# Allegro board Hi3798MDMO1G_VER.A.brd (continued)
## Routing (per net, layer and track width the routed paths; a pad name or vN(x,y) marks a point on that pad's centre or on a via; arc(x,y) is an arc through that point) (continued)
DDR_DQ11: length 9.7
  TOP w0.127: U1.169 43.2,43.38 42,44.58 42,45.72 41.5,46.23 39.46,46.23 39.08,45.84 39.08,44.65 U3.C2
DDR_DQ12: length 7.8
  TOP w0.127: U1.188 42.68,35.78 41.88,36.58 41.88,39.88 41.5,40.25 U3.A7
DDR_DQ13: length 5.3
  TOP w0.127: v2(43.66,42.55) 43.92,42.55 44.29,42.18 U1.172 ; U3.A2 v2(41.47,44.65)
  BOTTOM w0.127: v2(43.66,42.55) 43.66,42.8 41.8,44.65 v2(41.47,44.65)
DDR_DQ14: length 8.7
  TOP w0.127: U3.B8 40.67,39.85 41.27,39.85 41.5,39.62 41.5,36.32 42.44,35.38 U1.189
DDR_DQ15: length 5.1
  TOP w0.127: v2(42.64,42.55) 43.27,41.91 44.03,41.91 44.16,41.78 U1.173 ; U3.A3 v2(41.47,43.85)
  BOTTOM w0.127: v2(41.47,43.85) 41.47,43.72 v2(42.64,42.55)
DDR_DQ16: length 10.3
  TOP w0.127: U6.E3 v2(37.47,27.44) ; U1.201 44.06,30.58 43.81,30.83 v2(42.08,30.83)
  BOTTOM w0.127: v2(37.47,27.44) 37.47,28.1 38.19,28.83 38.19,29.34 39.69,30.83 v2(42.08,30.83)
DDR_DQ17: length 17.5
  TOP w0.127: U6.F7 37.46,23.45 37.46,22.83 37.63,22.66 38.11,22.66 38.26,22.52 38.26,21.24 38.6,20.9 42.69,20.9 43.65,19.95 48.89,19.95 49.53,20.59 49.53,21.27 49.92,21.66 49.92,21.68 49.95,21.71 U1.8
DDR_DQ18: length 10
  TOP w0.127: U6.F2 37.47,28.25 37.47,28.87 40.38,31.78 U1.198
DDR_DQ19: length 17.7
  TOP w0.127: U1.9 50.35,21.57 50.3,21.52 50.3,21.5 49.92,21.11 49.92,20.43 49.05,19.56 43.49,19.56 42.53,20.52 38.22,20.52 37.46,21.28 37.46,22.4 37.07,22.79 U6.F8
DDR_DQ20: length 12.1
  TOP w0.127: v2(42.77,31.37) 43.91,31.37 44.3,30.98 U1.200 ; U6.H3 v2(35.87,27.44)
  BOTTOM w0.127: v2(35.87,27.44) 36.68,27.44 37.05,27.81 37.05,28.19 37.81,28.96 37.81,29.49 39.69,31.37 v2(42.77,31.37)
DDR_DQ21: length 20.9
  TOP w0.127: U1.12 51.55,21.58 51.21,21.24 51.21,20.61 49.4,18.8 43.17,18.8 42.22,19.76 37.59,19.76 35.84,21.51 35.84,22.4 35.47,22.77 U6.H8
DDR_DQ22: length 11.3
  TOP w0.127: U1.197 40.15,32.18 37.81,29.84 37.05,29.84 36.67,29.46 36.67,28.24 U6.G2
DDR_DQ23: length 20.8
  TOP w0.127: U6.H7 35.87,23.44 35.87,22.85 36.06,22.66 36.46,22.66 36.64,22.49 36.64,21.34 37.84,20.14 42.37,20.14 43.33,19.18 49.24,19.18 50.83,20.77 50.83,21.4 51.15,21.72 U1.11
DDR_DQ24: length 14.7
  TOP w0.127: U6.D7 39.08,23.44 39.08,22.8 39.23,22.64 39.74,22.64 39.89,22.49 39.89,21.6 40.2,21.29 42.85,21.29 43.81,20.33 48.74,20.33 49.15,20.74 U1.6
DDR_DQ25: length 8.2
  TOP w0.127: U6.C3 39.88,27.45 39.88,29.62 40.1,29.84 41.37,29.84 41.84,29.38 U1.204
DDR_DQ26: length 11.9
  TOP w0.127: U6.C8 39.78,23.04 40.18,22.65 42.15,22.65 44.09,20.71 48.49,20.71 48.75,20.97 U1.5
DDR_DQ27: length 8.3
  TOP w0.127: U6.C2 39.06,28.25 39.06,29.44 39.91,30.29 41.56,30.29 42.07,29.78 U1.203
DDR_DQ28: length 8.3
  TOP w0.127: U1.2 47.55,21.69 47.33,21.47 44.41,21.47 42.03,23.84 U6.A7
DDR_DQ29: length 4.3
  TOP w0.127: U6.A2 41.58,27.84 42.27,28.54 43.83,28.54 43.87,28.58 U1.206
DDR_DQ30: length 9.9
  TOP w0.127: U6.B8 40.68,23.45 41.89,23.45 44.25,21.09 47.49,21.09 47.95,21.55 U1.3
DDR_DQ31: length 4.4
  TOP w0.127: U6.A3 41.49,27.04 42.63,28.18 U1.207
DDR_DQS0N: length 10.3
  TOP w0.114: U1.176 44.27,40.58 44.21,40.65 43.37,40.65 41.98,42.04 37.05,42.04 36.54,42.55 36.54,43.19 U3.G3
DDR_DQS0P: length 9.9
  TOP w0.114: U3.F3 36.8,43.19 36.8,42.66 37.16,42.3 42.09,42.3 43.48,40.91 44.21,40.91 44.27,40.98 U1.175
DDR_DQS1N: length 6.5
  TOP w0.114: U3.B7 40,40.52 40,40.71 40.19,40.89 42.01,40.89 42.51,40.39 42.51,40.01 43.08,39.45 44.21,39.45 44.27,39.38 U1.179
DDR_DQS1P: length 7
  TOP w0.114: U1.178 44.27,39.78 44.21,39.71 43.19,39.71 42.78,40.12 42.78,40.5 42.12,41.16 40.08,41.16 39.74,40.82 39.74,40.52 U3.C7
DDR_DQS2N: length 10.3
  TOP w0.114: U1.210 44.15,26.98 44.08,27.05 42.63,27.05 41.22,25.64 37.07,25.64 36.66,26.05 36.66,26.65 U6.G3
DDR_DQS2P: length 9.8
  TOP w0.114: U6.F3 36.92,26.9 36.92,26.16 37.18,25.9 41.11,25.9 42.52,27.31 44.08,27.31 44.15,27.38 U1.209
DDR_DQS3N: length 6.3
  TOP w0.114: U1.213 44.27,25.78 44.21,25.85 42.83,25.85 41.62,24.64 40.23,24.64 40,24.41 40,24.11 U6.B7
DDR_DQS3P: length 6.8
  TOP w0.114: U6.C7 39.74,24.11 39.74,24.52 40.12,24.9 41.51,24.9 42.72,26.11 44.21,26.11 44.27,26.18 U1.212
DDR_ODT: length 89.5
  TOP w0.127: U6.K1 34.18,28.95 34.18,29.8 v2(33.84,30.13) 33.57,30.41 33.56,30.41 30.03,33.94 v2(26.76,33.94) ; v1(65.75,20.95) 65.75,21.08 65.86,21.19 65.86,21.19 65.95,21.28 U1.48 ; U3.K1 v2(34.27,44.65)
  BOTTOM w0.127: v1(65.75,20.95) 65.33,20.95 64.72,20.34 64.13,20.34 61.89,18.1 58.25,18.1 55.96,15.81 53.9,15.81 50.03,11.94 34.45,11.94 27.53,18.86 27.53,19.46 24.99,22 24.99,32.17 v2(26.76,33.94) ; v2(33.84,30.13) 33.57,30.41 33.57,37.71 33.92,38.07 33.92,40.85 33.52,41.26 33.52,43.54 33.73,43.75 33.73,44.11 v2(34.27,44.65)
DDR_PLL: length 24.7
  TOP w0.203: U1.187 45.99,36.18 v1(46.25,35.92) ; v1(54.45,23.65) 54.75,23.35 U1.20
  TOP w0.381: v1(50.92,35.92) 50.92,29.38 53.18,27.11 v1(53.56,27.11)
  BOTTOM w0.381: v1(50.92,35.92) v1(46.25,35.92) 46.14,35.81 C264.1 ; C270.1 v1(54.45,23.65) C11.1 ; C11.1 55.81,27.11 LB7.1 ; C11.1 v1(53.56,27.11)
DDR_RASN: length 95.3
  TOP w0.127: U6.J3 34.67,27.31 35.01,27.65 35.01,28.96 34.77,29.21 34.77,30.1 v2(34,30.86) 30.26,34.6 v2(26.76,34.6) ; v1(63.59,18.03) 64.92,18.03 67.1,20.21 67.1,20.98 67.55,21.44 U1.52 ; U3.J3 v2(34.27,43.85)
  BOTTOM w0.127: v2(26.76,34.6) 24.61,32.45 24.61,20.17 33.98,10.79 50.5,10.79 54.38,14.67 56.44,14.67 58.72,16.95 62.37,16.95 63.45,18.03 v1(63.59,18.03) ; v2(34.27,43.85) 33.75,43.33 33.75,41.41 34.23,40.93 34.23,37.9 33.95,37.62 33.95,30.92 v2(34,30.86)
DDR_RESETN: length 80.1
  TOP w0.127: v1(61.56,19.94) 61.56,20.14 61.88,20.45 61.88,21.52 61.95,21.59 U1.38 ; v1(35.28,14.22) 35.16,14.1 29.7,14.1 24.76,19.05 24.76,24.12 25.61,24.98 25.61,25.29 25.61,25.51 26.86,26.76 C314.1 27.29,26.78 27.4,26.67 29.18,26.67 29.41,26.9 29.41,27.33 29.07,27.67 U6.T2 28.51,27.84 24.43,31.93 24.43,36.27 25.49,37.34 25.49,41.92 26.66,43.09 29.27,43.09 29.47,43.29 v2(29.47,43.85) U3.T2
  BOTTOM w0.127: v1(61.56,19.94) 60.83,19.94 60.13,19.24 57.78,19.24 55.49,16.95 52.5,16.95 49.01,13.46 36.04,13.46 v1(35.28,14.22) ; C313.1 29.46,43.85 v2(29.47,43.85)
DDR_VREF_A_CA: length 7.1
  TOP w0.203: U3.M8 32.68,39.05 32.68,38.39 32.95,38.12
  TOP w0.381: 32.95,38.12 32.95,38.04 32.99,38 C100.2 R60.2 C86.1 R55.1
DDR_VREF_A_DQ: length 3.9
  TOP w0.254: U3.H1 v2(35.07,45.45)
  BOTTOM w0.381: R75.1 C271.1 R54.2 C208.2 34.86,45.66 v2(35.07,45.45)
DDR_VREF_B_CA: length 7.6
  TOP w0.203: 32.86,21.71 32.65,21.92 32.65,22.86 32.47,23.04 U6.M8
  TOP w0.381: R93.1 C87.1 R92.2 C103.2 32.35,20.45 32.86,20.95 32.86,21.71
DDR_VREF_B_DQ: length 4.5
  TOP w0.305: U6.H1 35.55,28.72 v2(35.55,29.7)
  BOTTOM w0.381: R78.2 C223.2 R84.1 C308.1 35.65,29.81 v2(35.55,29.7)
DDR_WEN: length 80.1
  TOP w0.127: v1(62.54,19.91) 62.54,19.96 63.15,20.58 U1.41 ; U3.L3 33.07,42.87 31.13,40.93 28.59,40.93 27.02,39.36 27.02,36.32 25.95,35.26 25.95,33.07 28.29,30.73 28.92,30.73 29.56,30.1 31.21,30.1 31.86,29.45 31.86,28.48 32.07,28.28 32.32,28.28 32.61,27.99 32.61,27.73 33.07,27.28 U6.L3 33.07,26.24 31.34,24.51 28.46,24.51 27.35,23.4 27.35,19.58 30.8,16.13 31.09,15.84 v1(34.77,15.84)
  BOTTOM w0.127: v1(62.54,19.91) 62.06,20.4 60.74,20.4 59.97,19.62 57.62,19.62 55.33,17.33 52.34,17.33 48.85,13.84 36.76,13.84 v1(34.77,15.84)
FE_1V1: length 2.3
  TOP w0.203: U1.147 53.15,46.74 53.02,46.61 v1(52.96,46.61)
  BOTTOM w0.381: C248.1 52.96,47.31 v1(52.96,46.61)
FE_3V3: length 3.1
  TOP w0.203: v1(53.94,46.74) 54.1,46.74 54.35,46.99 U1.144 ; U1.148 52.75,47.17 52.32,46.74 v1(51.99,46.74)
HDMI_TX0N: length 40.9
  TOP w0.114: U1.126 61.55,48.73 61.49,48.8 61.49,49.22 57.23,53.48 56.1,53.48 43.49,66.09 43.49,73.52 43.61,73.64 U24.2 U24.9 43.61,75.64 43.49,75.76 43.49,76.2 44.24,76.95 44.24,77.74 44.67,78.17 J26.9
HDMI_TX0P: length 40.8
  TOP w0.114: U1.127 61.15,48.74 61.22,48.8 61.22,49.11 57.12,53.21 55.99,53.21 43.22,65.98 43.22,73.51 43.11,73.63 U24.1 U24.10 43.11,75.62 43.22,75.74 43.22,76.31 43.98,77.06 43.98,77.8 43.67,78.11 J26.7
HDMI_TX1N: length 41
  TOP w0.114: J26.6 43.17,78.23 42.71,77.76 42.71,76.98 41.81,76.09 41.81,75.81 41.93,75.69 U23.6 U23.5 41.93,73.7 41.82,73.58 41.82,66.5 55.87,52.45 57,52.45 59.89,49.56 59.89,48.8 59.95,48.74 U1.130
HDMI_TX1P: length 40.9
  TOP w0.114: J26.4 42.17,78.08 42.44,77.82 42.44,77.09 41.55,76.2 41.55,75.81 41.43,75.7 U23.7 U23.4 41.43,73.69 41.55,73.57 41.55,66.39 55.76,52.18 56.89,52.18 59.62,49.45 59.62,48.8 59.55,48.74 U1.131
HDMI_TX2N: length 41.3
  TOP w0.114: U1.132 59.15,48.74 59.09,48.8 59.09,49.11 56.62,51.57 55.45,51.57 41.12,65.94 40.3,66.76 40.3,73.44 40.43,73.57 U23.2 U23.9 40.43,75.61 40.31,75.73 40.31,76.28 41.33,77.3 41.33,77.79 41.67,78.12 J26.3
HDMI_TX2P: length 41.3
  TOP w0.114: U1.133 58.75,48.73 58.82,48.8 58.82,49 56.51,51.31 55.34,51.31 40.6,66.09 40.04,66.65 40.04,73.53 39.93,73.64 U23.1 U23.10 39.93,75.62 40.05,75.74 40.05,76.39 41.07,77.41 41.07,77.75 40.67,78.14 J26.1
HDMI_TX_1V1: length 2.1
  TOP w0.203: v1(61.94,46.74) 61.13,46.74 60.75,47.12 U1.128
HDMI_TX_3V3: length 1.2
  TOP w0.203: U1.129 60.35,46.92 v1(60.17,46.74)
HDMI_TX_CEC: length 41.5
  TOP w0.127: U1.123 62.75,48.64 63.22,49.11 63.22,49.58 57.69,55.12 56.74,55.12 46.87,64.98 R268.2 46.87,71.5 47.27,71.89 U4.3 47.26,72.47 46.23,72.47 45.75,72.94 45.75,74.98 46.67,75.89 J26.13
HDMI_TX_HOTPLUG: length 43.4
  TOP w0.127: U1.119 64.35,48.65 63.99,49.01 63.99,49.9 58.01,55.88 57.05,55.88 49.16,63.78 C149.1 R8.2 48.86,71.58 48.86,72.26 49.07,72.47 U4.4 51.49,72.47 52.74,73.73 52.74,75.09 51.37,76.46 51.37,76.77 49.67,78.47 J26.19
HDMI_TX_SCL: length 40.8
  TOP w0.127: U1.122 63.15,48.63 63.48,48.96 63.48,49.69 57.8,55.37 56.84,55.37 48.22,64 48.22,74.15 48,74.37 U4.1 47.27,75.35 47.65,75.73 R186.1 48.14,76.4 47.67,76.87 J26.15
HDMI_TX_SDA: length 40.8
  TOP w0.127: J26.16 48.17,78.09 49.92,76.34 R187.1 49.92,75.23 49.76,75.08 U4.6 49.02,74.37 48.57,73.93 48.57,64 56.95,55.63 57.9,55.63 63.73,49.8 63.73,48.85 63.55,48.67 U1.121
HDMI_TXCN: length 41.4
  TOP w0.114: U1.124 62.35,48.74 62.29,48.8 62.29,49.69 57.55,54.43 56.4,54.43 45,65.83 45,67.75 45.12,67.86 45.29,67.86 45.69,68.26 45.69,68.95 45.29,69.35 45.12,69.35 45,69.46 45,73.52 45.11,73.62 U24.5 U24.6 45.11,75.64 44.99,75.75 44.99,76.23 45.8,77.04 45.8,77.85 46.17,78.23 J26.12
HDMI_TXCP: length 41.4
  TOP w0.114: U1.125 61.95,48.73 62.02,48.8 62.02,49.58 57.44,54.17 56.29,54.17 44.74,65.72 44.74,67.86 45.01,68.13 45.18,68.13 45.42,68.37 45.42,68.84 45.18,69.08 45.01,69.08 44.74,69.35 44.74,73.52 44.61,73.65 U24.4 U24.7 44.61,75.67 44.72,75.79 44.72,76.34 45.53,77.15 45.53,77.85 45.17,78.21 J26.10
IR_IN: length 28.1
  TOP w0.127: U1.58 71.22,25.78 71.89,25.11 71.89,11.85 71.23,11.19 71.23,8.19 70.63,7.59 68.65,7.59 68.42,7.37 68.42,5.84 68.14,5.56 R140.1 67.79,2.86 D3.1
LED0_BASE: length 46.2
  TOP w0.127: R67.2 R26.2 17.48,65.52 17.05,65.09 17.05,63.69 17.75,62.99 21.16,62.99 22.95,61.2 22.95,59.82 25.19,57.58 43.38,57.58 51.55,49.4 U1.151
LED0_LINK_ACT: length 33
  TOP w0.127: R30.2 R79.2 v2(34.71,66.18) ; v1(34.71,58.09) 43.23,58.09 51.81,49.51 51.81,48.84 51.95,48.7 U1.150
  BOTTOM w0.127: v1(34.71,58.09) 35.65,59.04 35.65,65.23 v2(34.71,66.18)
LED_CTRL: length 29.3
  TOP w0.127: U1.57 71.24,25.38 71.63,24.98 71.63,11.95 70.97,11.29 70.97,8.39 70.43,7.85 67.43,7.85 66.41,8.86 66.41,9.6 66.24,9.78 R31.2 65.78,9.5 65.5,9.22 63.47,9.22 63.19,9.5 R51.1 R3.1
LED_GREEN: length 5.8
  TOP w0.254: LED1.3 64.63,3.56 64.22,3.96 Q2.3 65.56,5.76 R34.2
LED_RED: length 13.4
  TOP w0.254: Q1.3 60.28,4.31 59.55,3.57 LED1.1 ; Q1.3 59.6,5.74 59.43,5.56 R2.2 ; Q1.3 61.15,5.74 62.3,6.88 66.59,6.88 R22.1
NF_ALE_EMMC_PWREN: length 26.8
  TOP w0.127: U1.80 71.86,34.58 72,34.43 77.48,34.43 79.52,36.47 79.52,44.19 78.22,45.49 78.22,47.27 78.92,47.97 81.66,47.97 82.11,47.53 U19.17
NF_CLE: length 27.3
  TOP w0.127: U19.16 82.61,47.39 81.77,48.23 78.81,48.23 77.96,47.37 77.96,45.39 79.24,44.11 79.24,36.56 77.37,34.69 72.11,34.69 71.82,34.98 U1.81
NF_CSN0_EMMC_CMD: length 43
  TOP w0.127: U1.82 71.78,35.38 72.21,34.94 77.26,34.94 78.99,36.66 78.99,44 77.71,45.28 77.71,47.48 78.71,48.48 84.84,48.48 86.11,47.21 U19.9 86.11,44.8 85.63,44.32 85.63,43.25 83.45,41.06 v2(83.45,40.89)
  TOP w0.254: v2(85.31,38.36) 85.61,38.66 U22.W5
  BOTTOM w0.127: v2(85.31,38.36) 84.9,37.95 84.22,37.95 83.95,38.21 83.95,39.84 83.67,40.12 R212.2 83.32,40.76 83.45,40.89 v2(83.45,40.89)
NF_DQ0_EMMC_D0: length 23.9
  TOP w0.127: v2(86.84,32.26) 86.61,32.48 U22.H3 ; U19.29 80.61,28.44 81.5,29.34 v2(81.5,29.72) 80.57,30.65 77.44,30.65 74.94,33.15 71.45,33.15 71.21,33.38 U1.77
  BOTTOM w0.127: v2(81.5,29.72) 81.6,29.82 R189.2 82.87,29.82 83.28,30.23 83.28,31.11 84.42,32.26 v2(86.84,32.26)
NF_DQ1_EMMC_D1: length 26.8
  TOP w0.127: U22.H4 86.11,32.04 v2(85.69,31.62) ; v1(81.73,28.83) 81.11,28.21 U19.30 81.11,26 80.89,25.78 78.41,25.78 78.09,26.1 78.09,29.6 74.85,32.83 71.4,32.83 71.26,32.98 U1.76
  BOTTOM w0.127: v2(85.69,31.62) 84.3,31.62 83.66,30.99 83.66,29.46 83.05,28.85 R12.2 81.76,28.85 v1(81.73,28.83)
NF_DQ2_EMMC_D2: length 27.3
  TOP w0.127: U22.H5 85.61,32.68 84.73,31.8 84.73,29.57 84.5,29.34 82.9,29.34 81.61,28.05 U19.31 v1(81.61,25.46) 78.37,25.46 77.83,25.99 77.83,29.49 74.75,32.58 U1.75
  BOTTOM w0.127: R29.2 82.18,25.46 v1(81.61,25.46)
NF_DQ3_EMMC_D3: length 31
  TOP w0.089: U22.J2 86.86,33.62 86.86,33
  TOP w0.127: U1.73 71.24,31.78 71.34,31.68 75.29,31.68 77.58,29.39 77.58,25.89 78.96,24.51 v1(81.63,24.51) 82.11,24.99 U19.32 82.11,27.79 83.08,28.75 85.24,28.75 85.57,29.08 85.57,29.84 86.2,30.48 86.79,30.48 87.32,31.01 87.32,32.54 86.86,33
  BOTTOM w0.127: R58.2 80.87,25.27 v1(81.63,24.51)
NF_DQ4_EMMC_D4: length 33.6
  TOP w0.089: 86.36,33.01 86.36,33.62 U22.J3
  TOP w0.127: 86.36,33.01 86.36,31.72 86.71,31.37 v2(86.71,31.09) ; U1.72 75.23,31.38 77.33,29.28 77.33,25.78 79.24,23.86 86.34,23.86 86.87,24.4 86.87,25.13 86.61,25.39 U19.41 86.61,27.71 86.07,28.24 86.07,29.36 v2(86.71,30)
  BOTTOM w0.127: v2(86.71,30) v2(86.71,31.09) 86.76,31.03 R176.2
NF_DQ5_EMMC_D5: length 35.7
  TOP w0.089: 85.86,33.06 85.86,33.62 U22.J4
  TOP w0.127: v1(86.61,29.06) 86.61,28.22 87.11,27.72 U19.42 87.11,25.25 87.13,25.23 87.13,24.3 86.44,23.61 79.14,23.61 77.07,25.67 77.07,29.18 75.27,30.98 U1.71 ; v2(85.67,30.76) 85.3,31.13 85.3,31.86 85.86,32.42 85.86,33.06
  BOTTOM w0.127: R177.2 87.85,31.75 86.66,31.75 v2(85.67,30.76) 85.67,30 v1(86.61,29.06)
NF_DQ6_EMMC_D6: length 36.5
  TOP w0.089: U22.J5 85.61,33.77 85.36,33.52 85.36,33.22
  TOP w0.127: v2(84.27,30.96) 84.27,31.85 85.36,32.94 85.36,33.22 ; U1.70 75.31,30.58 76.82,29.07 76.82,25.57 79.03,23.36 86.55,23.36 87.61,24.42 U19.43 87.61,28.23 v2(87.29,28.55)
  BOTTOM w0.127: R188.2 87.62,29.49 87.62,28.83 87.34,28.55 v2(87.29,28.55) 87.24,28.5 86.4,28.5 84.27,30.63 v2(84.27,30.96)
NF_DQ7_EMMC_D7_BOOT_SEL0: length 37.8
  TOP w0.089: U22.J6 84.86,33.62 84.86,32.99 84.61,32.74
  TOP w0.127: v1(88.11,28.07) U19.44 88.11,24.56 86.65,23.1 78.93,23.1 76.56,25.46 76.56,28.96 75.35,30.18 U1.69 ; 84.61,32.74 83.79,31.92 83.79,30.38 v2(84.22,29.95)
  BOTTOM w0.127: v1(88.11,28.07) 88.15,28.1 R202.2 ; v1(88.11,28.07) 88.21,27.97 R33.1 ; v1(88.11,28.07) 86.33,28.07 84.45,29.95 v2(84.22,29.95)
NF_RDY0_EMMC_RST: length 48.4
  TOP w0.127: U1.85 71.47,36.58 71.99,36.06 76.92,36.06 78.07,37.21 78.07,43.56 76.87,44.77 76.87,48.07 78.07,49.28 85.44,49.28 87.11,47.61 U19.7 87.11,44.3 89.63,41.78 89.63,38.22 88.74,37.33 v2(88.72,37.33)
  TOP w0.254: v2(86.09,35.99) 86.09,37.43 85.65,37.87 U22.U5
  BOTTOM w0.127: v2(86.09,35.99) 86.09,36.5 86.92,37.33 C115.1 R203.2 v2(88.72,37.33)
NF_REN_EMMC_CLK: length 38.1
  TOP w0.127: v2(84.25,41.15) 84.3,41.15 85.95,42.8 86.25,42.8 86.61,43.16 U19.8 86.61,47.34 85.08,48.87 78.43,48.87 77.31,47.75 77.31,44.96 78.53,43.74 78.53,36.91 77.11,35.48 R59.1
  TOP w0.254: v2(84.44,38.37) 84.64,38.37 85.11,38.84 U22.W6
  BOTTOM w0.127: v2(84.44,38.37) 84.44,38.5 84.25,38.68 v2(84.25,41.15)
NF_WEN_EMMC_DET: length 23.1
  TOP w0.127: U19.18 81.61,43.65 79.77,41.81 79.77,36.37 77.58,34.18 U1.79 69.67,34.18 v1(69.31,34.54)
  BOTTOM w0.381: R56.2 v1(69.31,34.54)
NF_WP: length 4.9
  TOP w0.254: v2(80.76,43.58) 81.11,43.94 U19.19
  BOTTOM w0.381: R215.2 R89.1 80.74,43.57 v2(80.76,43.58)
PWR_OFF/ON: length 3.1
  TOP w0.127: U1.102 71.27,43.38 71.6,43.05 v1(71.6,42.93)
  BOTTOM w0.127: R40.1 71.52,43.59 R41.1 71.49,43.03 v1(71.6,42.93)
RECOVERY: length 56.6
  TOP w0.127: U1.103 71.81,43.78 72.23,44.2 v1(72.23,45.85) ; v1(62.32,54.61) 61.94,54.61 59.28,57.28 59.28,65.79 59.78,66.29 63.47,66.29 64.86,67.69 64.86,68.96 66.35,70.45 67.26,70.45 67.56,70.74 R25.2 C138.2 67.56,83.85 S1.2
  BOTTOM w0.127: v1(62.32,54.61) 64.1,54.61 64.86,53.85 67.43,53.85 70.17,51.1 70.17,48.94 71.72,47.39 71.72,46.35 v1(72.23,45.85)
RF0: length 8.6
  TOP w0.127: L1.2 C135.1 14.44,11.83 arc(14.72,11.89) 14.96,12.05 17.12,14.22 arc(17.79,15.2) 18.02,16.37 U7.3
RF1: length 4
  TOP w0.127: U2.7 15.05,16.24 arc(14.93,15.64) 14.59,15.13 C50.1 L7.2
RFF0: length 3
  TOP w0.127: J5.1 10.69,10.84 arc(10.94,10.89) 11.15,11.03 arc(11.29,11.24) 11.34,11.49 C61.1 L1.1
RFF1: length 3
  TOP w0.127: L7.1 C60.1 11.34,15.01 arc(11.29,15.27) 11.14,15.48 arc(10.92,15.63) 10.67,15.68 J4.1
RX+_PHY0: length 34.7
  TOP w0.114: R63.1 26.89,60.68 26.89,60.2 27.28,59.81 28.45,59.81 28.57,59.69 U8.6 U8.3 30.55,59.69 30.67,59.81 43.79,59.81 54.82,48.78 54.82,48.67 54.75,48.61 U1.143
RX-_PHY0: length 34.7
  TOP w0.114: U1.142 55.15,48.61 55.09,48.67 55.09,48.89 43.9,60.08 30.67,60.08 30.55,60.2 U8.4 U8.5 28.57,60.2 28.45,60.08 27.39,60.08 27.16,60.31 27.16,60.69 R64.1
SDIO0_CARD_DETECT: length 44.6
  TOP w0.127: J21.9 v1(12.77,61.78) ; v1(18.78,55.52) 21.66,55.52 23.59,53.59 41.6,53.59 45.93,49.27 46.98,49.27 47.55,48.69 U1.161
  BOTTOM w0.127: v1(12.77,61.78) 14.71,59.85 14.71,56.62 14.9,56.43 17.89,56.43 18.1,56.23 R155.2 18.86,55.6 v1(18.78,55.52)
SDIO0_CCLK_OUT: length 39.8
  TOP w0.127: J21.5 9.72,56.54 9.89,56.71 13.48,56.71 14.09,57.33 22.52,57.33 24.22,55.63 41.88,55.63 R5.2
SDIO0_CCMD: length 46.4
  TOP w0.127: U1.157 49.15,48.73 48.61,49.28 48.05,49.28 47.28,50.04 46.32,50.04 41.62,54.74 24.2,54.74 22.34,56.6 15.04,56.6 12.42,53.98 v1(10.07,53.98) 9.71,54.34 J21.3
  BOTTOM w0.127: v1(10.07,53.98) 10.08,53.97 R153.2
SDIO0_CDATA0: length 48.4
  TOP w0.127: U1.154 50.35,49.88 43.17,57.07 24.98,57.07 23.59,58.47 15.25,58.47 15.04,58.47 14.05,59.46 10.82,59.46 v1(10.1,58.74) J21.7
  BOTTOM w0.127: R152.2 10.18,58.82 v1(10.1,58.74)
SDIO0_CDATA1: length 48.6
  TOP w0.127: U1.153 50.75,48.63 50.7,48.69 50.61,48.78 50.61,49.99 43.27,57.32 25.09,57.32 23.69,58.72 15.15,58.72 14.02,59.84 v1(10.1,59.84) J21.8
  BOTTOM w0.127: R151.2 10.8,59.84 v1(10.1,59.84)
SDIO0_CDATA2: length 45.5
  TOP w0.127: U1.160 47.95,48.65 47.07,49.53 46.03,49.53 41.58,53.98 23.83,53.98 21.78,56.03 15.64,56.03 11.75,52.14 v1(9.99,52.14) J21.1
  BOTTOM w0.127: R156.2 10.45,51.68 v1(9.99,52.14)
SDIO0_CDATA3: length 45.9
  TOP w0.127: U1.159 48.35,48.85 48.18,49.02 47.94,49.02 47.18,49.78 46.13,49.78 41.43,54.48 23.97,54.48 22.11,56.35 15.27,56.35 11.93,53.01 v1(10.06,53.01) 9.82,53.24 J21.2
  BOTTOM w0.127: R154.2 10.24,52.83 v1(10.06,53.01)
SDIO0_CWPR: length 2.3
  TOP w0.203: v1(51.1,49.15) 51.15,49.1 U1.152
  BOTTOM w0.203: R43.1 50.77,48.81 v1(51.1,49.15)
SDIO0_PWREN: length 23.1
  TOP w0.127: R76.1 26.48,52.78 R149.1 42.06,52.78 45.94,48.9 46.83,48.9 47.1,48.62 U1.162
SDIO_3318: length 55.9
  TOP w0.203: C22.1 49.95,49.46 U1.155
  TOP w0.305: v1(13.05,58.82) 13.92,58.82 14.7,58.04 22.95,58.04 24.61,56.39 42.13,56.39 48.23,50.29 48.42,50.29 C22.1
  BOTTOM w0.305: R151.1 R152.1 ; R152.1 11.62,58.44 11.32,58.14 9.92,58.14 9.44,57.65 9.44,55.06 9.84,54.66 11.52,54.66 11.72,54.45 R153.1 R154.1 R156.1 ; R152.1 v1(13.05,58.82)
SPDIF_OUT_BOOT_SEL1: length 2.2
  TOP w0.127: U1.117 65.15,48.58 v1(64.7,49.03)
  BOTTOM w0.127: v1(64.7,49.03) 64.43,49.3 R39.1
STANDBY_PWROFF: length 171.7
  TOP w0.127: v1(67.79,8.31) 67.79,9.5 R98.1 67.66,9.68 R81.1 ; v1(15.27,38.27) 15.32,38.23 R44.1 ; v1(71.52,7.54) 71.48,7.58 71.48,11.08 72.15,11.76 72.15,25.48 v1(71.72,25.91) 71.45,26.18 U1.59
  BOTTOM w0.127: v1(15.27,38.27) 11.39,38.27 10.2,37.08 10.2,26.33 30.56,5.97 65.17,5.97 67.51,8.31 v1(67.79,8.31) 70.76,8.31 v1(71.52,7.54) 71.72,7.54 71.93,7.75 81.81,7.75 84.42,10.36 84.42,18.14 82.16,20.4 82.16,21.8 78.15,25.81 78.15,42.83 76.91,44.07 76.17,44.07 72.87,47.37 72.1,47.37 70.71,48.77 R73.1 ; R88.1 v1(71.72,25.91)
TX+_PHY0: length 36
  TOP w0.114: U1.146 53.55,48.76 53.56,48.77 53.37,48.96 43.54,58.79 30.67,58.79 30.55,58.67 U8.1 U8.8 28.57,58.67 28.45,58.79 25.5,58.79 24.47,59.82 24.47,60.69 R61.1
TX-_PHY0: length 36.1
  TOP w0.114: R62.1 24.74,60.69 24.74,59.93 25.61,59.06 28.45,59.06 28.57,59.18 U8.7 U8.2 30.55,59.18 30.67,59.06 43.65,59.06 53.56,49.15 53.83,48.88 53.83,48.73 53.95,48.61 U1.145
UART0_RXD: length 32.1
  TOP w0.127: U1.60 71.71,26.58 72.45,25.84 72.45,16.27 74.47,14.25 74.47,6.02 v1(76.04,4.45) ; J18.2 79.38,3.95 v1(79.5,4.06) R136.2
  BOTTOM w0.127: v1(76.04,4.45) 76.68,3.81 79.24,3.81 v1(79.5,4.06)
UART0_TXD: length 30.1
  TOP w0.127: J18.3 78.13,3.77 77.72,4.18 R135.2 77.72,5.64 77.49,5.87 75.05,5.87 74.72,6.2 74.72,14.38 72.7,16.4 72.7,25.99 71.71,26.98 U1.61
USB0_DM: length 40.3
  TOP w0.152: U1.140 55.95,48.81 55.92,48.85 55.92,49.44 v1(56.13,49.65) ; J12.2 83.08,61.64 82.88,61.84 81.14,61.84 D6.1 C141.1 79.22,61.7 78.93,61.7 v1(78.71,61.48)
  BOTTOM w0.152: v1(56.13,49.65) 55.92,49.87 55.92,57.74 58.25,60.07 71.37,60.07 72.99,61.7 78.5,61.7 v1(78.71,61.48)
USB0_DP: length 40.3
  TOP w0.152: U1.141 55.55,48.81 55.59,48.85 55.59,49.44 v1(55.37,49.65) ; v1(78.71,62.24) 78.93,62.03 79.22,62.03 C139.1 D1.1 80.85,62.17 82.77,62.17 83.08,62.48 J12.3
  BOTTOM w0.152: v1(55.37,49.65) 55.59,49.87 55.59,57.88 58.11,60.4 71.23,60.4 72.86,62.03 78.5,62.03 v1(78.71,62.24)
USB01_1V1: length 2
  TOP w0.203: v1(58.13,46.58) 57.66,46.58 57.17,47.07 57.17,47.19 57.15,47.21 U1.137
USB01_3V3: length 2.1
  TOP w0.203: U1.139 56.35,46.99 55.91,46.55 v1(55.34,46.55)
USB1_DM: length 78.4
  TOP w0.152: v1(18.58,32.18) 18.36,32.39 18.2,32.39 18.09,32.29 18.09,31.52 18.32,31.29 19.15,31.29 19.54,30.9 U7.7 ; v1(33.84,61.13) 34.12,61.42 34.12,61.71 34.47,62.05 43.54,62.05 55.05,50.55 56.36,50.55 57.92,48.98 57.92,48.72 57.95,48.69 U1.135
  BOTTOM w0.152: v1(18.58,32.18) 18.36,32.39 16.95,32.39 16.56,32.79 16.56,33.31 16.33,33.54 16.18,33.54 16.03,33.69 J2.4 16.03,36.81 16.86,37.64 16.86,37.97 17.3,38.4 20.14,38.4 22.01,40.26 22.01,53.35 26.95,58.29 31.9,58.29 34.12,60.51 34.12,60.85 v1(33.84,61.13)
USB1_DP: length 78.4
  TOP w0.152: U1.136 57.55,48.69 57.59,48.72 57.59,48.85 56.22,50.22 54.91,50.22 43.4,61.72 34.6,61.72 34.45,61.57 34.45,61.42 v1(34.73,61.13) ; v1(18.58,32.94) 18.36,32.72 18.06,32.72 17.76,32.43 17.76,31.47 17.59,31.29 16.21,31.29 16.04,31.11 U7.6
  BOTTOM w0.152: v1(18.58,32.94) 18.36,32.72 17.09,32.72 16.89,32.92 16.89,33.31 17.12,33.54 17.87,33.54 18.03,33.69 J2.3 18.03,36.81 17.19,37.64 17.19,37.83 17.43,38.07 20.28,38.07 22.34,40.13 22.34,53.21 27.09,57.96 32.04,57.96 34.45,60.37 34.45,60.85 v1(34.73,61.13)
USB2_DM: length 31.1
  TOP w0.152: U1.89 71.34,38.18 71.38,38.21 71.84,38.21 71.99,38.06 71.99,37.86 v1(71.72,37.59)
  BOTTOM w0.152: J13.2 81.47,14.1 81.16,14.1 80.03,15.23 80.03,21.29 76.6,24.71 76.6,31.95 72,36.55 72,37.31 v1(71.72,37.59)
USB2_DP: length 31.1
  TOP w0.152: U1.90 71.39,38.58 71.42,38.54 71.97,38.54 72.32,38.2 72.32,37.88 v1(72.61,37.59)
  BOTTOM w0.152: J13.3 81.46,14.43 81.3,14.43 80.36,15.37 80.36,21.42 76.93,24.85 76.93,32.09 72.33,36.69 72.33,37.31 v1(72.61,37.59)
USB_BOOT: length 7.8
  TOP w0.127: U1.108 69.9,45.83 69.75,45.97 69.75,47.56 v1(71.21,49.02)
  BOTTOM w0.127: R42.2 72.33,47.9 v1(71.21,49.02)
VDAC_3V3: length 1.2
  TOP w0.203: U1.112 v1(67.15,46.74)
XIN: length 14.7
  TOP w0.203: U1.63 72.9,27.78 75.13,25.55 R1.2 75.13,21.39 C364.1 75.18,21.06 75.46,20.78 75.91,20.78 76.17,20.52 76.17,18.41 75.83,18.07 X2.1
XOUT: length 10.8
  TOP w0.203: R14.1 75.94,21.54 R1.1 75.94,22.96 75.53,23.37 75.53,25.78 73.13,28.18 U1.64
$4N774: length 14.3
  TOP w0.127: R7.2 60.67,56.4 61.9,55.18 62.64,55.18 62.83,54.99 62.83,54.12 67.05,49.9 69.47,49.9 69.59,50.02 C71.1 70.55,50.42 R21.1
$4N775: length 7.3
  TOP w0.381: v1(62.2,58.93) 61.59,58.93 R70.1 61.46,58.24 R99.2 R53.1 61.66,56.39 C76.1 ; U11.6 v1(64.17,58.93)
  BOTTOM w0.381: v1(62.2,58.93) v1(64.17,58.93)
$4N782: length 9.6
  TOP w0.127: U11.1 64.17,54.8 64.61,54.36 v1(65.12,54.36)
  BOTTOM w0.127: R73.2 C8.1 69.97,51.66 67.28,54.36 v1(65.12,54.36)
$4N811: length 4.7
  TOP w0.381: U13.6 61.49,11.37 61.27,11.58 R13.2 R110.1 C82.1 R101.1
$4N812: length 74
  TOP w0.127: v1(60.29,8.76) 60.06,8.99 59.33,8.99 59.12,9.19 R102.2 ; v1(72.26,46.74) 72.41,46.89 72.41,49.23 72.13,49.5 C72.1 R23.1
  BOTTOM w0.127: v1(72.26,46.74) 73.14,46.74 76.06,43.81 76.8,43.81 77.9,42.72 77.9,25.7 81.91,21.69 81.91,20.29 84.17,18.03 84.17,10.46 81.71,8 71.55,8 70.99,8.56 68.52,8.56 68.32,8.76 67.6,8.76 67.03,8.19 60.86,8.19 v1(60.29,8.76)
$4N813: length 1
  TOP w0.127: R102.1 59.91,9.8 R110.2
$4N818: length 2.8
  TOP w0.381: R81.2 C5.1 66.56,11.37 U13.1
$4N881: length 5
  TOP w0.381: U15.5 12.06,40.52 11.72,40.18 R52.1 12.23,39.19 12.33,39.29 R10.1 C84.1
$4N883: length 3.3
  TOP w0.381: R44.2 17.03,38.24 C30.1 R6.2 16.06,39.8 15.89,39.97 U15.1
$4N953: length 3.2
  TOP w0.508: U14.5 v1(61.18,65.38)
  BOTTOM w0.381: R105.1 R100.1 61.21,65.41 v1(61.18,65.38)
$4N955: length 5.7
  TOP w0.508: U14.1 68.77,61.57 69.06,61.85 v1(69.06,61.98)
  BOTTOM w0.381: D4.1 70.2,63.96 68.98,62.74 R95.1 68.32,62.59 68.66,62.24 68.66,62.23 68.92,61.98 v1(69.06,61.98)
$4N956: length 1.7
  BOTTOM w0.381: C83.2 60.48,63.41 62.01,63.41 R104.1
$4N957: length 3.1
  TOP w0.508: U14.6 v1(61.18,64.11)
  BOTTOM w0.381: C83.1 61.13,64.16 v1(61.18,64.11) 61.21,64.14 61.79,64.14 C24.1
$4N958: length 2.4
  TOP w0.508: v1(61.18,62.84) U14.7
  BOTTOM w0.381: R4.2 61.72,62.69 61.33,62.69 v1(61.18,62.84)
$4N975: length 2.2
  TOP w0.508: v1(61.18,61.57) U14.8
  BOTTOM w0.381: v1(61.18,61.57) 61.15,61.59 C44.1
$4N980: length 1.4
  BOTTOM w0.381: R95.2 C65.1
$4N983: length 2.1
  TOP w0.508: U14.3 v1(69.06,64.11)
  BOTTOM w0.381: v1(69.06,64.11) 69.03,64.14 C65.2
$4N998: length 1.1
  TOP w0.381: R70.2 60.65,58.67 60.67,58.65 R7.1
$5N541: length 5.1
  TOP w0.254: R144.2 73.88,10.41 73.5,10.03 Q4.3 72.36,7.98 R118.2
$5N542: length 5.9
  TOP w0.254: R118.1 73.27,8.99 v1(73.25,9.02)
  BOTTOM w0.254: Q13.1 71.15,10.41 C6.2 71.66,9.91 Q14.1 72.99,9.27 v1(73.25,9.02)
$5N549: length 2.7
  TOP w0.127: R98.2 68.7,9.91 69.69,9.91 70.07,10.29 Q4.1
$6N1407: length 2.2
  TOP w0.203: U1.149 v1(52.35,49.09)
  BOTTOM w0.203: R173.1 51.78,48.52 v1(52.35,49.09)
$6N2392: length 2.9
  TOP w0.127: R59.2 72.08,35.48 71.38,36.18 U1.84
$6N2441: length 4.7
  TOP w0.127: U1.156 49.55,48.84 48.74,49.66 48.1,49.66 46.86,50.89 R5.1
$6N2475: length 3.2
  TOP w0.203: U1.138 v1(56.75,46.48)
  BOTTOM w0.381: v1(56.75,46.48) 56.75,46.4 56.46,46.1 R85.2 R82.2
$6N2516: length 11.5
  BOTTOM w0.127: R42.1 C136.1 75.15,45.72 75.86,45.01 S2.1 78.64,45.01 79.37,45.75 82.6,45.75 S2.2
$6N2574: length 2.8
  TOP w0.203: X2.3 77.95,20.4 C365.1 77.92,21.34 R14.2
$7N1997: length 6.9
  TOP w0.127: R87.2 76.19,36.93 76.03,37.1 73.26,37.1 73.09,36.93 R24.2 72.02,36.58 71.21,37.38 U1.87
$7N2001: length 2.3
  TOP w0.203: U1.111 67.55,47.02 67.84,46.74 v1(68.04,46.74)
  BOTTOM w0.381: R32.2 68.29,46.99 v1(68.04,46.74)
$7N2021: length 2.4
  TOP w0.203: U1.113 66.75,47.1 66.73,47.08 66.73,47.07 66.27,46.61 v1(66.26,46.61)
  BOTTOM w0.381: C250.2 v1(66.26,46.61)
$8N1926: length 4.6
  TOP w0.114: U1.17 53.55,21.71 51.77,19.92 51.77,19.58 51.52,19.33 51.06,19.33 R18.2
$8N1927: length 4.7
  TOP w0.114: U1.18 53.95,21.73 52.03,19.81 52.03,19.47 51.69,19.12 R35.2
$8N1992: length 2.5
  TOP w0.203: R45.1 68.55,20.17 68.55,21.46 68.4,21.61 U1.54
$9N2491: length 3.4
  TOP w0.127: U1.55 69.8,24.53 69.38,24.95 v1(69.38,26.29)
  BOTTOM w0.127: C255.2 v1(69.38,26.29)
$10N1177: length 2.1
  TOP w0.127: U3.L8 v2(32.67,39.85)
  BOTTOM w0.127: v2(32.67,39.85) 32.67,40.1 32.49,40.28 32.4,40.36 32.27,40.49 R46.2
$11N1382: length 1.2
  TOP w0.127: U6.L8 v2(33.47,23.44)
  BOTTOM w0.127: R71.2 33.54,23.52 v2(33.47,23.44)
$12N1699: length 2.3
  TOP w0.254: R80.2 85.08,25.4 85.11,25.4 U19.38
$12N1717: length 2.4
  TOP w0.254: R68.1 86.35,24.93 85.61,25.67 U19.39
$12N1720: length 2.9
  TOP w0.089: U22.K2 87.36,34.12 v2(88.02,34.12)
  BOTTOM w0.203: 88.04,34.12 v2(88.02,34.12) ; 88.04,34.12 88.42,34.5 C124.1 ; 88.04,34.12 87.41,34.75 C123.1
$13N792:
  vias: v1(86.84,74.42) v1(86.84,73.53) v1(87.72,74.42) v1(87.72,73.53)
$13N808: length 1.8
  TOP w0.381: U10.3 80.29,72.1 80.49,71.91 R15.1
$13N809: length 1.9
  TOP w0.381: U10.4 82.2,72.1 81.76,71.65 R48.2
$13N815: length 1.6
  TOP w0.381: R11.1 75.35,13.12 U12.3
$13N860: length 1.6
  TOP w0.381: R47.2 75.41,8.93 U12.4
$14N750: length 6.5
  TOP w0.127: R178.1 69.09,5.52 C47.1 70.62,5.56 C177.1 72.1,2.13 D3.3
$14N753: length 19.1
  TOP w0.127: v1(17.89,55.55) 18.4,55.04 21.51,55.04 23.79,52.76 R76.2
  BOTTOM w0.127: v1(17.89,55.55) 17.31,56.13 14.77,56.13 14.45,56.45 14.45,59.47 Q5.1
$14N801: length 1.8
  TOP w0.254: Q2.1 66.24,8.05 R22.2
$14N806: length 1.8
  TOP w0.127: R3.2 61.28,8.04 Q1.1
$15N1014: length 2.5
  TOP w0.305: R49.1 60.93,69.47 60.86,69.54 U5.11
$15N1015: length 1.5
  TOP w0.203: R194.2 57.49,61.48 58.14,60.83 C350.1
$15N1016: length 3.6
  TOP w0.203: R20.2 R28.2 C316.1 R194.1
$15N1019: length 7.9
  TOP w0.203: U5.13 58.36,70.84 57.06,69.54 57.06,66.52 C54.2 57.16,66.08 56.68,65.6 R28.1
$15N1039: length 1.5
  TOP w0.203: C351.2 54.01,60.75 54.47,61.21 R193.1
$15N1040: length 7.9
  TOP w0.203: U5.2 55.38,70.84 56.42,69.79 56.42,67.02 C55.1 55.81,65.78 R27.2
$15N1043: length 3.6
  TOP w0.203: R193.2 C317.1 R27.1 R19.1
$15N1047: length 14
  TOP w0.203: R19.2 53.88,65.3 C55.2 55,66.59 55.79,67.38 55.79,69.66 55.28,70.17 54.02,70.17 U5.3 53.11,70.19 52.87,70.42 52.87,71.82 53.43,72.39 55.24,72.39 R146.1 R74.2
$15N1073: length 2.1
  TOP w0.356: C33.2 52.61,67.76 53.09,68.24 U5.6
$15N1074: length 2.7
  TOP w0.356: U5.7 v1(55.15,67.59)
  BOTTOM w0.381: v1(55.15,67.59) 55.23,67.5 C32.1
$15N1075: length 2.4
  TOP w0.356: U5.8 v1(58.71,67.59)
  BOTTOM w0.381: C32.2 58.63,67.5 v1(58.71,67.59)
$15N1098: length 13.2
  TOP w0.203: R20.1 58.07,66.31 C54.1 57.82,66.57 57.82,69.28 58.72,70.19 U5.12 60.64,70.19 60.94,70.49 60.94,71.8 60.59,72.15 58.75,72.15 58.35,72.55 R145.1 R72.1
$15N1099: length 2
  TOP w0.381: R91.2 R49.2 R57.1
$15N1107: length 3.3
  TOP w0.356: C363.1 52.74,68.9 52.75,68.89 U5.5
  TOP w0.381: R66.1 52.13,69.66 52.04,69.57 C363.1
$16N1155: length 3.3
  TOP w0.508: T2.7 v1(28.38,66.15)
  BOTTOM w0.381: C297.1 27.87,65.64 v1(28.38,66.15) 28.96,65.57 C154.1
$16N1157: length 10
  TOP w0.381: R67.1 17.18,68.06 17.18,76.04 J25.9
$16N1158: length 15.4
  TOP w0.381: R79.1 34.04,76.64 32.67,78.01 30.58,78.01 J25.11
$16N1159: length 12.4
  BOTTOM w0.508: R270.2 25.51,78.79 J25.8 27.34,82.65 J25.7
$16N1160: length 2.8
  TOP w0.508: T2.15 22.03,72.55 22.28,72.3 v1(22.56,72.3)
  BOTTOM w0.508: R271.2 22.22,72.64 v1(22.56,72.3)
$16N1161: length 2.7
  TOP w0.508: T2.10 v1(28.38,72.15)
  BOTTOM w0.508: v1(28.38,72.15) 27.89,72.64 R269.2
$16N1163: length 12.8
  TOP w0.254: T2.9 29.65,74.51 29.17,74.99 28.63,74.99 28.05,75.58 23.68,79.94 23.68,80.4 23.86,80.58 25.27,80.58 J25.6
$16N1164: length 11.8
  TOP w0.254: T2.11 27.11,74.64 27.54,75.07 27.54,75.51 23.28,79.78 J25.3
$16N1166: length 12
  TOP w0.254: J25.1 21.24,82.76 20.46,81.98 20.46,80.05 22.36,78.14 22.36,76 21.88,75.52 21.88,75.09 21.65,74.87 20.99,74.87 20.76,74.64 T2.16
$16N1167: length 11.8
  TOP w0.254: J25.2 21.63,82.26 21.31,82.26 20.86,81.81 20.86,80.22 22.77,78.31 22.77,75.83 22.28,75.35 22.28,75.04 22.49,74.84 23.07,74.84 23.3,74.61 T2.14
$16N1168: length 11.4
  BOTTOM w0.508: R272.2 23.73,73.54 24.29,74.1 J25.4 25.31,82.65 J25.5
$16N1169: length 3.2
  TOP w0.508: T2.2 v1(22.03,66.15)
  BOTTOM w0.381: C153.1 21.65,65.77 v1(22.03,66.15) 22.61,65.57 C307.1
$16N1187: length 6.3
  TOP w0.114: T2.1 20.76,63.79 21.05,63.5 21.8,63.5 21.93,63.37 21.93,63 22.33,62.6 24.37,62.6 24.47,62.49 24.47,62.25 R61.2
$16N1188: length 6.2
  TOP w0.114: T2.3 23.3,63.72 23.08,63.5 22.32,63.5 22.19,63.37 22.19,63.12 22.44,62.87 24.48,62.87 24.74,62.6 24.74,62.25 R62.2
$16N1189: length 5.1
  TOP w0.114: R63.2 26.89,62.25 26.89,62.6 27.16,62.88 28.05,62.88 28.28,63.1 28.28,63.37 28.15,63.5 27.4,63.5 27.11,63.79 T2.6
$16N1190: length 5.1
  TOP w0.114: T2.8 29.65,63.72 29.43,63.5 28.67,63.5 28.54,63.37 28.54,62.99 28.16,62.61 27.27,62.61 27.15,62.49 27.15,62.25 R64.2
$18N880: length 1.3
  TOP w0.127: R268.1 D19.1

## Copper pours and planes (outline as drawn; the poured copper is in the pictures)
1V1_CORE on TOP (solid shape): outline of 272 points within 47.85,15.62 71.34,46.99
1V1_CORE on BOTTOM (solid shape): 70.33,33.66 70.33,33.02 70.2,32.89 68.01,32.89 67.91,32.99 67.91,33.15 69.82,33.15 69.82,33.4 69.56,33.4 69.56,33.15 67.91,33.15 67.91,33.68 68.01,33.78 70.2,33.78
1V1_CORE on BOTTOM (solid shape): 72.1,23.85 72.1,19.68 71.95,19.53 69.18,19.53 68.8,19.91 68.8,21.72 69.44,21.72 69.44,21.97 69.18,21.97 69.18,21.72 68.8,21.72 68.8,22.23 69.44,22.23 69.44,22.48 69.18,22.48 69.18,22.23 68.8,22.23 68.8,22.73 67.79,23.75 67.79,25.15 68.04,25.4 70.55,25.4
1V1_CORE on BOTTOM (solid shape): 65.14,47.02 65.14,46.58 64.99,46.43 64.99,45.59 64.86,45.47 64.86,44.83 63.59,44.83 63.47,44.96 63.47,45.09 64.48,45.09 64.48,45.21 64.23,45.21 64.23,45.09 63.47,45.09 63.47,45.72 64.61,45.72 64.61,45.97 64.36,45.97 64.36,45.72 63.47,45.72 63.47,46.23 63.59,46.35 64.36,46.35 64.48,46.48 64.48,46.99 64.61,47.12 65.04,47.12
1V1_CPU on TOP (solid shape): outline of 101 points within 69.69,38.86 76.8,55.5
1V1_CPU on BOTTOM (solid shape): 75.15,52.07 75.15,49.78 74.9,49.53 72.99,49.53 71.85,50.67 71.85,51.56 72.48,51.56 72.48,51.82 72.23,51.82 72.23,51.56 71.85,51.56 71.85,52.04 71.98,52.17 75.05,52.17
1V1_CPU on BOTTOM (solid shape): 75.53,41.78 75.53,39.12 75.41,38.99 71.34,38.99 71.21,39.12 71.21,39.37 74.14,39.37 74.14,39.62 73.88,39.62 73.88,39.37 73.12,39.37 73.12,39.62 72.87,39.62 72.87,39.37 72.1,39.37 72.1,39.75 71.85,39.75 71.85,39.37 71.21,39.37 71.21,40.13 71.85,40.13 71.85,40.39 71.6,40.39 71.6,40.13 71.21,40.13 71.21,41.15 71.98,41.15 71.98,41.4 71.6,41.4 71.6,41.15 71.21,41.15 71.21,41.66 71.47,41.91 75.41,41.91
1V5_DDR3 on TOP (solid shape): 24.35,46.27 24.35,39.12 23.46,38.23 21.05,38.23 20.92,38.35 21.43,38.35 21.43,38.61 21.18,38.61 21.18,38.35 20.92,38.35 20.92,38.86 21.43,38.86 21.43,39.12 21.18,39.12 21.18,38.86 20.92,38.86 20.92,42.15 20.71,42.36 20.18,42.36 19.95,42.59 19.95,46.33 20.15,46.53 24.1,46.53
1V5_DDR3 on TOP (solid shape): 48.1,43.96 48.1,43.03 47.97,42.9 47.97,23.88 47.26,23.16 47.26,21.77 47.21,21.72 44.67,21.72 44.42,21.97 44.42,23.75 44.8,24.13 45.82,24.13 45.82,24.13 45.95,24.26 45.95,24.88 46,24.95 46.08,24.95 46.7,25.38 46.08,25.81 46,25.81 45.95,25.87 45.95,26.88 45.94,26.88 45.94,29.74 45.99,29.83 46.09,29.83 46.63,30.18 46.09,30.53 45.99,30.53 45.94,30.62 45.94,33.34 45.99,33.43 46.09,33.43 46.63,33.78 46.09,34.13 45.99,34.13 45.94,34.22 45.94,35.49 45.99,35.57 46.09,35.58 46.32,35.55 46.53,35.66 46.6,36.06 46.28,36.31 46.19,36.3 46.12,36.38 46.19,36.45 46.28,36.45 46.6,36.7 46.53,37.09 46.32,37.21 46.09,37.18 45.99,37.19 45.94,37.27 45.94,38.54 45.99,38.63 46.09,38.63 46.63,38.98 46.09,39.33 45.99,39.33 45.94,39.42 45.94,43.34 45.99,43.43 46.09,43.43 46.63,43.78 46.09,44.13 45.99,44.13 45.94,44.22 45.94,45.09 46.07,45.21 46.85,45.21
1V5_DDR3 on BOTTOM (solid shape): 37.63,43.19 37.63,41.49 37.55,41.42 36.39,41.42 36.3,41.5 36.29,41.54 36.29,42.96 36.59,43.26 37.56,43.26
1V5_DDR3 on BOTTOM (solid shape): 36.29,26.42 36.42,26.29 37.18,26.29 37.31,26.16 37.31,24.51 36.8,24 35.78,24 35.65,24.13 35.65,24.38 36.42,24.38 36.42,24.64 36.04,24.64 36.04,24.38 35.65,24.38 35.65,24.66 35.67,24.68 35.7,24.72 35.72,24.77 35.73,24.82 35.73,24.88 35.73,24.93 35.72,24.98 35.7,25.03 35.67,25.07 35.65,25.09 35.65,25.27 35.53,25.4 35.53,26.29 36.04,26.29 36.04,26.67 35.65,26.67 35.65,26.29 35.53,26.29 35.53,26.92 35.65,27.05 36.29,27.05
1V5_DDR3 on POWER03 (solid shape): outline of 6256 points within 23.07,10.67 66.9,47.8
3V3 on TOP (solid shape): 70.96,59.69 70.96,57.91 70.71,57.66 67.4,57.66 66.9,57.15 65.75,57.15 65.75,59.18 66.39,59.18 66.39,59.44 66.13,59.44 66.13,59.18 65.75,59.18 65.75,59.69 65.88,59.82 70.83,59.82
3V3 on TOP (solid shape): 63.21,15.24 63.21,13.08 63.09,12.95 61.69,12.95 61.05,12.32 59.53,12.32 59.28,12.57 59.28,14.1 60.04,14.86 62.83,14.86 62.83,15.11 62.58,15.11 62.58,14.86 60.04,14.86 60.55,15.37 63.09,15.37
3V3 on TOP (solid shape): 14.33,46.63 14.33,44.45 14.11,44.22 14.11,42.11 14.05,42.06 11.97,42.06 11.87,42.16 11.87,43.05 13.68,43.05 13.68,43.43 13.3,43.43 13.3,43.05 11.87,43.05 11.87,43.69 13.68,43.69 13.68,44.07 13.3,44.07 13.3,43.69 11.87,43.69 11.87,46.58 12.05,46.76 14.21,46.76
3V3 on TOP (solid shape): 73.88,69.85 73.88,67.94 73.75,67.82 65.5,67.82 65.31,68.01 65.31,68.07 65.88,68.07 65.88,68.33 65.75,68.33 65.75,68.07 65.31,68.07 65.31,68.9 66.52,70.1 73.63,70.1
3V3 on BOTTOM (solid shape): 14.31,46.53 14.31,44.37 14.16,44.22 11.95,44.22 11.82,44.34 11.82,46.53 11.97,46.68 14.16,46.68
3V3 on BOTTOM (solid shape): 74.52,30.23 74.52,29.34 74.39,29.21 72.99,29.21 72.23,28.45 71.6,28.45 71.47,28.57 71.47,28.96 71.72,29.21 72.1,29.21 72.23,29.34 72.23,29.72 74.39,29.72 74.39,29.97 74.26,29.97 74.26,29.72 74.01,29.72 74.01,29.97 73.75,29.97 73.75,29.72 72.23,29.72 72.23,29.97 72.36,30.1 73.5,30.1 73.75,30.35 74.39,30.35
3V3 on POWER03 (solid shape): outline of 9789 points within 8.86,3.94 79.6,70.36
3V3_MOS on TOP (solid shape): 65.75,28.32 65.75,27.18 65.63,27.05 58.01,27.05 57.75,27.3 57.75,28.19 58.01,28.45 65.63,28.45
3V3_MOS on BOTTOM (solid shape): 15.33,53.89 15.33,52.88 15.2,52.75 13.93,52.75 13.8,52.88 13.8,53.89 13.93,54.02 15.2,54.02
3V3_MOS on BOTTOM (solid shape): 69.31,13.59 69.31,11.94 69.18,11.81 66.01,11.81 65.75,12.06 65.75,13.59 66.01,13.84 69.06,13.84
3V3_MOS on BOTTOM (solid shape): 21.5,27.1 21.5,25.45 21.37,25.32 18.7,25.32 18.58,25.45 18.58,27.1 18.7,27.22 21.37,27.22
3V3_MOS on BOTTOM (solid shape): 52.8,44.45 52.8,42.29 52.65,42.14 51.96,42.14 51.78,42.32 51.78,44.45 51.91,44.58 52.67,44.58
3V3_MOS on BOTTOM (solid shape): 58.64,28.32 58.64,26.8 58.39,26.54 57.12,26.54 56.99,26.67 56.99,28.32 57.12,28.45 58.51,28.45
3V3_MOS on BOTTOM (solid shape): 55.7,44.09 55.7,42.04 55.59,41.94 54.93,41.94 54.83,42.04 54.83,44.12 54.93,44.22 55.57,44.22
3V3_MOS on BOTTOM (solid shape): 60.8,44.2 60.8,42.34 60.72,42.27 60.01,42.27 59.91,42.37 59.91,43.69 60.42,43.69 60.42,43.94 60.29,43.94 60.29,43.69 59.91,43.69 59.91,44.2 60.04,44.32 60.67,44.32
3V3_MOS on BOTTOM (solid shape): 66.52,28.83 66.52,27.18 66.39,27.05 65.25,27.05 64.99,27.3 64.99,27.43 66.01,27.43 66.01,27.81 65.75,27.81 65.75,27.43 64.99,27.43 64.99,28.57 65.27,28.85 66.49,28.85
3V3_MOS on BOTTOM (solid shape): 72.87,59.26 72.87,56.9 72.74,56.77 71.21,56.77 70.83,57.15 59.84,57.15 59.73,57.25 59.73,58.34 59.86,58.47 71.21,58.47 72.13,59.39 72.74,59.39
3V3_MOS on BOTTOM (solid shape): 68.52,36.09 70.28,36.09 70.33,36.04 70.33,35.51 70.25,35.43 67.91,35.43 67.76,35.28 65.63,35.28 65.5,35.41 65.5,35.64 69.87,35.64 69.87,35.86 69.67,35.86 69.67,35.64 65.5,35.64 65.5,36.58 65.63,36.7 67.91,36.7
3V3_MOS on BOTTOM (solid shape): 19.14,60.75 19.14,56.94 19.01,56.82 16.85,56.82 16.73,56.94 16.73,57.15 18.76,57.15 18.76,57.53 18.38,57.53 18.38,57.15 16.73,57.15 16.73,58.67 17.49,58.67 17.49,59.05 17.11,59.05 17.11,58.67 16.73,58.67 16.73,59.31 17.49,59.31 17.49,59.69 17.11,59.69 17.11,59.31 16.73,59.31 16.73,60.75 16.85,60.88 19.01,60.88
3V3_MOS on BOTTOM (solid shape): 68.93,44.58 68.93,44.12 69.01,44.04 70.9,44.04 71,43.94 71,42.84 70.88,42.72 69.36,42.72 69.06,42.42 68.17,42.42 68.15,42.43 68.05,42.43 67.96,42.52 67.96,43.18 70.83,43.18 70.83,43.43 70.58,43.43 70.58,43.18 69.82,43.18 69.82,43.43 69.69,43.43 69.69,43.18 67.96,43.18 67.96,44.58 68.09,44.7 68.8,44.7
3V3_MOS on POWER03 (solid shape): outline of 6403 points within 13.81,12.06 71.21,70.36
3V3_MOS_FLASH on TOP (solid shape): 76.29,59.31 76.29,57.78 76.04,57.53 71.6,57.53 71.47,57.66 71.47,59.56 71.6,59.69 75.91,59.69
3V3_MOS_FLASH on BOTTOM (solid shape): outline of 687 points within 73.88,23.88 89.88,59.44
3V3_SD on TOP (solid shape): 10.65,56.21 10.65,55.19 10.5,55.04 8.4,55.04 8.3,55.14 8.3,55.77 8.4,55.88 9.71,55.88 9.84,56 9.84,56.21 9.99,56.36 10.5,56.36
3V3_SD on BOTTOM (solid shape): 14.69,55.93 14.7,55.93 14.77,55.86 17.3,55.86 17.36,55.8 17.36,52.88 17.23,52.75 15.84,52.75 15.71,52.88 15.71,54.15 15.58,54.28 13.42,54.28 12.66,55.04 9.99,55.04 9.87,55.16 9.87,56.31 9.99,56.43 14.19,56.43
3V3_WIFI on TOP (solid shape): 23.28,30.78 23.28,28.75 23.15,28.62 22.77,28.62 21.21,27.07 21.19,27.07 21.07,27.08 20.97,27.05 20.86,26.98 20.79,26.87 20.77,26.84 20.57,26.84 20.55,26.87 20.23,27.08 19.9,26.87 19.89,26.84 14,26.84 13.88,26.97 13.88,27.73 14.39,28.24 20.23,28.24 20.99,29 20.99,30.78 21.24,31.03 23.02,31.03
3V3_WIFI on BOTTOM (solid shape): 14.77,37 14.77,33.7 15.53,32.94 15.53,27.99 16.04,27.48 17.69,27.48 18.07,27.1 18.07,25.45 17.94,25.32 17.18,25.32 16.42,26.08 13.75,26.08 13.24,26.59 13.24,37 13.5,37.26 14.51,37.26
5V0 on TOP (solid shape): 82.52,80.87 82.52,77.09 82.52,76.58 82.14,76.2 81.23,76.2 79.11,76.2 77.31,74.4 77.31,74.4 77.23,74.32 77.23,72.08 77.76,71.55 77.76,62.3 77.46,62 69.56,62 69.21,62.36 70.33,62.36 70.33,62.61 70.07,62.61 70.07,62.36 69.82,62.36 69.82,62.61 69.56,62.61 69.56,62.36 66.77,62.36 66.72,62.41 66.72,63.12 66.85,63.25 69.69,63.25 70.2,63.75 74.14,63.75 74.39,64.01 74.39,69.98 74.01,70.36 72.87,70.36 72.74,70.48 73.5,70.48 73.5,70.74 73.12,70.74 73.12,70.48 72.74,70.48 72.74,75.95 73.94,77.14 75.79,77.14 77.79,79.15 77.79,79.7 79.37,81.28 82.11,81.28
5V0 on BOTTOM (solid shape): 74.26,13.84 74.26,11.56 74.01,11.3 71.01,11.3 70.78,11.53 70.78,12.88 72,14.1 74.01,14.1
5V0 on BOTTOM (solid shape): 82.58,80.5 82.58,77 82.33,76.74 78.36,76.74 76.93,75.31 76.93,70.1 76.68,69.85 74.64,69.85 74.33,70.16 74.33,75.91 78.2,79.78 78.2,80.47 79.28,81.55 81.54,81.55
5V0 on POWER03 (solid shape): outline of 1215 points within 72.23,10.79 80.87,73.91
5V0_MOS on TOP (solid shape): 80.59,13.82 80.59,11.28 80.36,11.05 77.06,11.05 76.93,11.18 76.93,14.1 77.18,14.35 80.05,14.35
5V0_MOS on TOP (solid shape): 81.25,75.82 81.25,73.91 80.98,73.65 77.65,73.65 77.56,73.74 77.56,74.3 79.22,75.95 81.12,75.95
5V0_MOS on BOTTOM (solid shape): 76.93,14.35 79.6,14.35 80.61,13.34 80.61,11.18 79.85,10.41 74.9,10.41 74.64,10.67 74.64,12.83 75.91,12.83 75.92,12.77 75.93,12.72 75.95,12.66 75.98,12.62 76.01,12.57 76.05,12.53 76.1,12.5 76.15,12.48 76.2,12.46 76.25,12.45 76.31,12.44 76.36,12.45 76.42,12.47 76.47,12.49 76.52,12.52 76.56,12.55 76.6,12.59 76.63,12.64 76.65,12.69 76.67,12.74 76.68,12.8 76.68,12.85 76.67,12.91 76.65,12.96 76.63,13.01 76.6,13.06 76.56,13.1 76.52,13.14 76.47,13.17 76.42,13.19 76.36,13.2 76.31,13.21 76.25,13.21 76.2,13.2 76.15,13.18 76.1,13.15 76.05,13.12 76.01,13.08 75.98,13.04 75.95,12.99 75.93,12.94 75.92,12.88 75.91,12.83 74.64,12.83 74.64,14.61 75.02,14.99 76.29,14.99
5V0_MOS on POWER03 (solid shape): outline of 3091 points within 52.16,10.79 87.72,77.34
AVDD11_PLL012 on BOTTOM (solid shape): 70.45,30.73 70.45,30.15 70.4,30.1 69.28,30.1 69.16,30.23 68.17,30.23 67.89,29.95 67.23,29.95 67.15,30.02 67.15,30.38 70,30.38 70,30.53 69.79,30.53 69.79,30.38 67.15,30.38 67.15,30.4 68.62,30.4 68.62,30.61 68.37,30.61 68.37,30.4 67.15,30.4 67.15,30.73 67.2,30.78 70.4,30.78
AVDD33_PLL01 on BOTTOM (solid shape): 70.33,28.83 70.33,28.27 70.28,28.22 69.67,28.22 69.51,28.07 67.53,28.07 67.4,28.07 67.28,28.19 67.28,28.32 68.55,28.32 68.55,28.45 69.94,28.45 69.94,28.57 69.69,28.57 69.69,28.45 68.55,28.45 68.55,28.57 68.42,28.57 68.42,28.32 67.28,28.32 67.28,28.83 67.4,28.96 70.2,28.96
AVDD33_USB2 on BOTTOM (solid shape): 70.33,38.23 70.33,37.85 70.2,37.72 68.55,37.72 68.29,37.47 66.26,37.47 66.13,37.59 66.13,37.85 70.07,37.85 70.07,37.97 69.69,37.97 69.69,37.85 66.13,37.85 66.13,38.23 66.26,38.35 70.2,38.35
GND on TOP (solid shape): 86.84,41.09 86.84,40.59 86.81,40.52 86.8,40.45 86.8,40.43 86.56,40.2 86.55,40.19 86.36,40.08 86.28,39.88 86.28,39.86 86.12,39.7 86.05,39.7 85.96,39.72 85.94,39.81 85.93,39.95 85.87,40.07 85.86,40.08 85.86,40.1 86.07,40.3 86.05,40.59 86.05,41.19 86.17,41.31 86.62,41.31
GND on TOP (solid shape): 16.56,46.63 16.56,44.45 16.5,44.4 15.27,44.4 14.89,44.02 14.89,41.95 15.04,41.8 18.81,41.8 18.87,41.87 19.08,41.87 19.31,42.1 20.23,42.1 20.39,41.94 20.39,38.46 20.29,38.35 17.62,38.35 17.49,38.48 20.16,38.48 20.16,38.61 19.91,38.61 19.91,38.48 17.49,38.48 17.49,38.86 20.16,38.86 20.16,39.12 19.91,39.12 19.91,38.86 18.26,38.86 18.26,39.24 17.87,39.24 17.87,38.86 17.49,38.86 17.49,39.42 18.32,39.42 18.32,39.8 17.94,39.8 17.94,39.42 17.49,39.42 17.49,40.41 16.82,41.09 15.14,41.09 15,40.95 15,40.03 14.9,39.93 14.51,39.93 14.38,40.05 14.38,40.95 14.25,41.08 12.9,41.08 12.82,41.16 12.82,41.73 12.87,41.78 14.42,41.78 14.42,42.09 14.41,42.09 14.41,43.81 14.83,43.81 14.83,43.97 14.57,43.97 14.57,43.81 14.41,43.81 14.41,44.1 14.91,44.59 14.91,46.59 15.06,46.74 16.45,46.74
GND on TOP (solid shape): outline of 111 points within 27.78,30.23 39.34,38.3
GND on TOP (solid shape): outline of 86 points within 82.96,35.18 85.87,38.09
GND on TOP (solid shape): outline of 394 points within 33.88,62.48 57.93,87.84
GND on TOP (solid shape): outline of 5831 points within 7.59,0.51 93.07,87.84
GND on BOTTOM (solid shape): 14.22,58.17 14.22,56.98 14.19,56.94 9.99,56.94 9.87,57.07 9.87,57.65 10.05,57.83 11.62,57.83 12.08,58.29 14.1,58.29
GND on BOTTOM (solid shape): 39.57,25.55 40.1,25.55 40.23,25.43 40.23,24.54 40.07,24.38 39.16,24.38 38.7,24.84 37.99,24.84 37.94,24.89 37.94,26.04 38.07,26.16 38.96,26.16
GND on BOTTOM (solid shape): outline of 11786 points within 7.59,0.51 93.07,87.84
GND on GND02 (solid shape): outline of 23693 points within 7.59,0.51 93.07,87.84
GND on POWER03 (solid shape): outline of 2264 points within 35.38,23.72 63.85,47.8
GND on POWER03 (solid shape): outline of 4618 points within 7.59,0.51 93.07,87.84
FE_3V3 on BOTTOM (solid shape): 54.07,47.7 54.07,45.47 53.92,45.31 51.94,45.31 51.91,45.34 51.78,45.34 51.66,45.47 51.66,46.86 51.78,46.99 52.52,46.99 52.57,46.94 52.57,46.35 52.7,46.23 53.38,46.23 53.49,46.33 53.49,47.12 53.94,47.12 53.94,47.37 53.82,47.37 53.82,47.12 53.49,47.12 53.49,47.68 53.56,47.75 54.02,47.75
HDMI_TX_1V1 on BOTTOM (solid shape): 62.45,47.47 62.45,45.09 62.96,44.58 64.74,44.58 64.86,44.45 64.86,43.94 64.74,43.81 61.82,43.81 61.69,43.94 61.69,44.2 64.48,44.2 64.48,44.32 64.1,44.32 64.1,44.2 61.69,44.2 61.69,45.39 61.99,45.39 61.99,45.62 61.84,45.62 61.84,45.39 61.69,45.39 61.69,45.9 62.1,45.9 62.1,46.05 61.87,46.05 61.87,45.9 61.69,45.9 61.69,46.35 61.56,46.48 61.56,47.12 62.07,47.12 62.07,47.37 61.82,47.37 61.82,47.12 61.56,47.12 61.56,47.68 61.61,47.73 62.2,47.73
HDMI_TX_3V3 on BOTTOM (solid shape): 60.44,46.36 60.45,46.36 60.45,46.22 60.52,46.15 60.52,45.21 60.6,45.14 60.6,44.65 60.55,44.6 59.91,44.6 59.86,44.65 59.86,44.96 60.29,44.96 60.29,45.21 60.17,45.21 60.17,44.96 59.86,44.96 59.86,45.47 60.29,45.47 60.29,45.72 60.17,45.72 60.17,45.47 59.86,45.47 59.86,47.12 60.29,47.12 60.29,47.37 60.17,47.37 60.17,47.12 59.86,47.12 59.86,47.68 59.91,47.73 60.44,47.73
Net_163 on BOTTOM (solid shape): 32.42,81 29.75,81 29.75,82.27 32.42,82.27
Net_164 on BOTTOM (solid shape): 20.86,81 18.2,81 18.2,82.27 20.86,82.27
Net_165 on BOTTOM (solid shape): 31.4,82.77 28.74,82.77 28.74,84.04 31.4,84.04
Net_166 on BOTTOM (solid shape): 19.85,82.77 17.18,82.77 17.18,84.04 19.85,84.04
USB01_1V1 on BOTTOM (solid shape): 58.29,47.73 58.29,47.12 58.51,46.89 58.51,44.58 58.39,44.45 57.88,44.45 57.75,44.58 57.75,44.96 58.26,44.96 58.26,45.21 58.13,45.21 58.13,44.96 57.75,44.96 57.75,45.47 58.26,45.47 58.26,45.72 58.13,45.72 58.13,45.47 57.75,45.47 57.75,47.12 58.13,47.12 58.13,47.37 58.01,47.37 58.01,47.12 57.75,47.12 57.75,47.7 57.8,47.75 58.26,47.75
USB01_3V3 on BOTTOM (solid shape): 56.91,47.83 56.91,47.35 56.89,47.32 56,47.32 55.62,46.94 55.62,44.96 55.57,44.91 54.86,44.91 54.81,44.96 54.81,47.5 56.48,47.5 56.48,47.75 56.23,47.75 56.23,47.5 54.81,47.5 54.81,47.73 54.93,47.85 56.89,47.85
VDAC_3V3 on BOTTOM (solid shape): 67.53,47.62 67.53,46.41 67.35,46.23 67.35,43.74 67.3,43.69 66.63,43.69 66.5,43.81 66.5,46.24 66.9,46.63 66.9,47.12 67.28,47.12 67.28,47.37 67.15,47.37 67.15,47.12 66.9,47.12 66.9,47.62 67.02,47.75 67.4,47.75
$4N777 on TOP (solid shape): 67.15,55.63 69.18,55.63 69.31,55.5 69.31,52.2 69.07,51.96 67.39,51.96 65.75,53.59 65.75,56.01 65.88,56.13 66.64,56.13
$4N814 on TOP (solid shape): 71.09,14.22 71.09,12.57 70.96,12.45 67.53,12.45 67.24,12.74 67.17,12.84 67.06,12.92 67.02,12.95 66.87,12.95 64.36,12.95 64.23,13.08 64.23,14.35 64.36,14.48 70.83,14.48
$4N882 on TOP (solid shape): 18.88,42.24 18.7,42.06 15.3,42.06 15.15,42.21 15.15,43.91 15.38,44.15 16.99,44.15 16.99,46.23 18.88,46.23
$4N983 on TOP (solid shape): 74.01,65.41 74.01,64.26 73.88,64.14 69.82,64.14 69.44,63.75 66.77,63.75 66.71,63.81 66.71,64.51 66.81,64.61 68.79,64.61 69.17,64.99 69.18,64.99 69.72,65.53 73.88,65.53
$13N791 on TOP (solid shape): 83.41,11.43 83.41,10.16 80.99,7.75 77.18,7.75 76.93,8 76.93,10.16 77.18,10.41 80.23,10.41 81.5,11.68 83.15,11.68
$13N792 on TOP (solid shape): 88.11,74.55 88.11,73.41 87.85,73.15 83.91,73.15 83.41,73.66 82.01,73.66 82.01,75.79 82.11,75.9 86.76,75.9
$13N792 on BOTTOM (solid shape): 90.72,72.57 90.72,62.84 85.52,57.63 84.6,57.63 84.14,57.18 81.93,57.18 81.65,57.45 81.65,58.95 81.81,59.11 83.43,59.11 88.33,64.01 88.33,71.37 86.33,73.38 86.33,74.68 86.58,74.93 88.36,74.93
$14N755 on BOTTOM (solid shape): 16.31,63.74 16.31,62.82 16.14,62.66 13.17,62.66 13.04,62.78 13.04,63.8 13.17,63.93 16.12,63.93
